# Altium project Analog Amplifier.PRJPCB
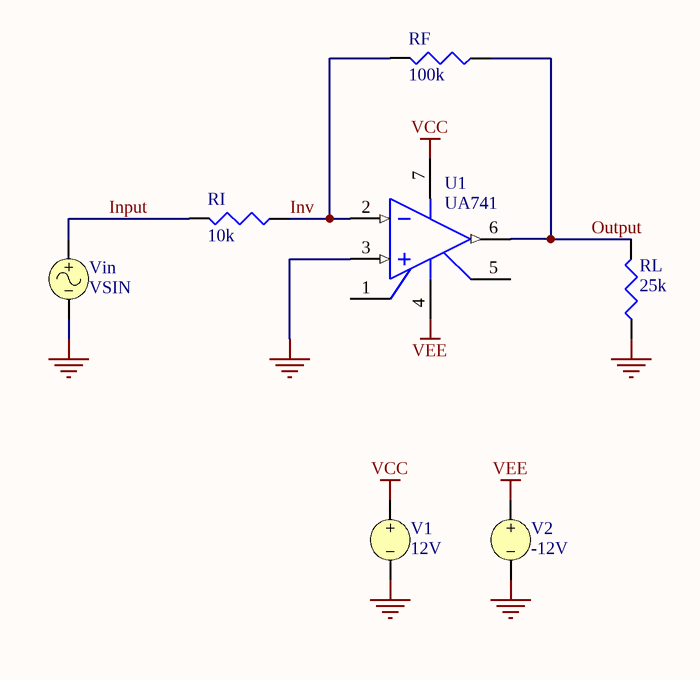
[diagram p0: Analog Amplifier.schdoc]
1 sheet, 7 parts. Net scope: global (net labels, ports and power ports of the same name join across sheets).

## Sheet Analog Amplifier.schdoc: Analog Amplifier
size A4; Organization: Altium Limited; Address1: L3, 12a Rodborough Rd; Address2: Frenchs Forest; Address3: NSW; Address4: Australia 2086; DocumentNumber: 1; SheetNumber: 1; SheetTotal: 1

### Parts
RF  100k
RI  10k
RL  25k
U1  UA741
V1  12V
V2  -12V
Vin  VSIN

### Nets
GND: RL.2(BOT) U1.3(+IN) V1.2 V2.2 Vin.2
VCC: U1.7(V+) V1.1
VEE: U1.4(V-) V2.1
Input: RI.1(TOP) Vin.1
Inv: RF.1(TOP) RI.2(BOT) U1.2(-IN)
Output: RF.2(BOT) RL.1(TOP) U1.6(OUT)

Not connected (* = marked no-connect by the designer): U1 1(OFFSET_NULL_1) 5(OFFSET_NULL_2)

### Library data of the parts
RF RI RL = RES: Resistor
U1 = UA741: General-Purpose Operational Amplifier
V1 V2 = VSRC: Voltage Source
Vin = VSIN: Sinusoidal Voltage Source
